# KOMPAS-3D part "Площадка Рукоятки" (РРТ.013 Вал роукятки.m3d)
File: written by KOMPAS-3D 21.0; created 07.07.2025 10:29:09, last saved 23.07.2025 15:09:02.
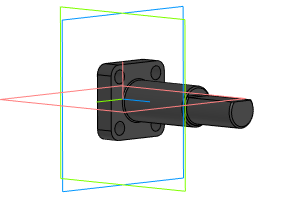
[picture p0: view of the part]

Document properties: Автор: User; Полное имя файла: C:\Users\User\Desktop\Ручной ротатор КД\Модели КД\РРТ.013 Вал роукятки.m3d

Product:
- Part/product: Площадка Рукоятки
    Масса: 0.05069
    Форматы листов документа: A4@4~2
  - Body: Тело 1
      Масса: 0.050771

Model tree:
1. Эскиз:1
2. Элемент выдавливания:1
     Расстояние 1 = 4
3. Скругление:1  (with: Элемент выдавливания:1)
     Радиус = 3
4. Эскиз:2  (with: Элемент выдавливания:1)
5. Элемент выдавливания:2
     Расстояние 1 = 26
6. Эскиз:3  (with: Элемент выдавливания:2)
7. Элемент выдавливания:3
     Расстояние 1 = 18
8. Элемент выдавливания:4  (with: Элемент выдавливания:1)
     Расстояние 1 = 2
9. Скругление:2  (with: Элемент выдавливания:4)
     Радиус = 0.4
10. Скругление:3  (with: Элемент выдавливания:3)
     Радиус = 0.4
11. Фаска:1  (with: Элемент выдавливания:1, Элемент выдавливания:2, Элемент выдавливания:3)
     Угол = 45; Длина 1 = 0.5; Длина 2 = 0.5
